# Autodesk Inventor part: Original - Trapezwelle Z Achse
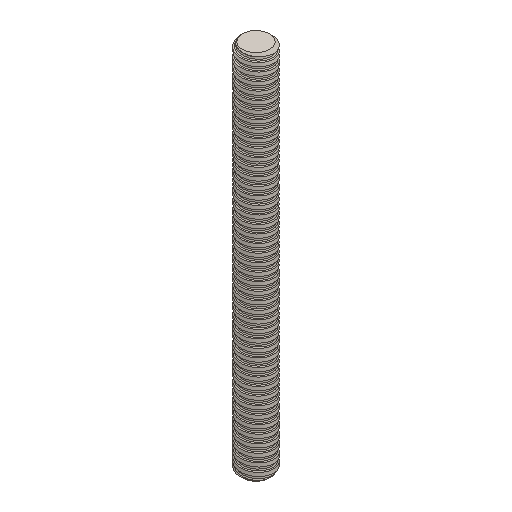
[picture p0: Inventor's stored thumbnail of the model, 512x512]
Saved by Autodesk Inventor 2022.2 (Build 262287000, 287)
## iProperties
Created: 2024-09
Part Number: Original - Trapezwelle Z Achse
Material: Generico
Document SubType Name: Modeling
Designer: 18907419
Density: 1 g/cm^3
Appearance: Default
Author: 18907419
Revision Number: ANY
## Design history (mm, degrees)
feature "Schnitt-Rotation1"
node "Solido1"
